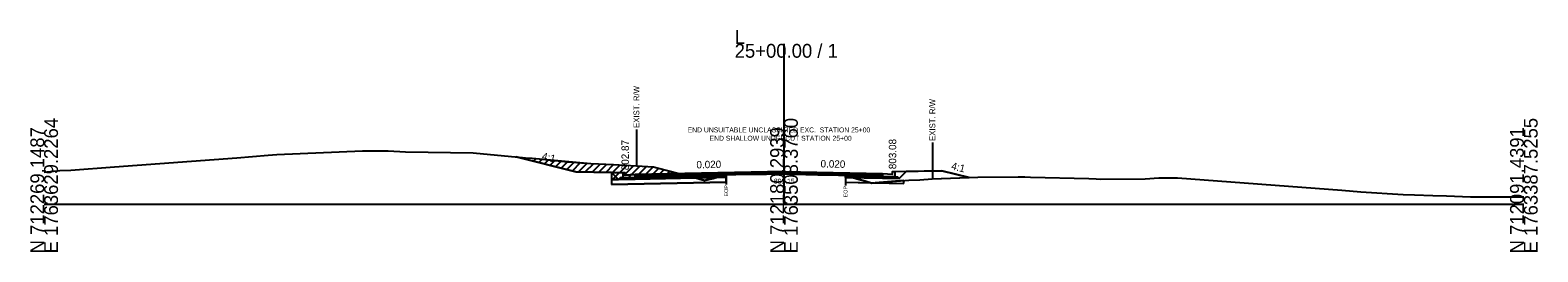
# Model space of a CAD drawing. Extents: x -26 to 5303, y -10 to 9578.
# Drawn here: x 997.2 to 1302.8, y 4990.3 to 5035.3 of the extents above; entities that cross this region are included whole.
import ezdxf

# ---------------------------------------------------------------- set-up
doc = ezdxf.new("R2010")
doc.units = 0
for name, color, linetype in [('Default', 7, 'Continuous'), ('Exist CMT Pavement', 7, 'Continuous'), ('Exist Cross Section Cell', 7, 'Continuous'), ('Exist XS Ground Line', 7, 'Continuous'), ('Old_Level_10', 7, 'Continuous'), ('Old_Level_3', 7, 'Continuous'), ('Old_Level_4', 7, 'Continuous'), ('Prop CMT Conc Surface', 7, 'Continuous'), ('Prop CMT Concrete Structures', 7, 'Continuous'), ('Prop CMT Pvmt Course 1', 7, 'Continuous'), ('Prop CMT Pvmt Course 1 CG', 7, 'Continuous'), ('Prop CMT Pvmt Course 2', 7, 'Continuous'), ('Prop CMT Pvmt Course 3', 7, 'Continuous'), ('Prop CMT Pvmt Surface', 7, 'Continuous'), ('Prop CMT Slope Grass', 7, 'Continuous'), ('Prop CMT Subgrade Earthwork', 7, 'Continuous'), ('Prop Shade Light', 7, 'Continuous'), ('Prop XS Earthwork Shape', 7, 'Continuous'), ('Prop XS Hydro Elevations', 7, 'Continuous'), ('Prop XS SE Text', 7, 'Continuous'), ('Prop XS Side Slope Text', 7, 'Continuous'), ('Prop XS Wedging', 7, 'Continuous'), ('Scratch_Level_5', 7, 'Continuous')]:
    doc.layers.add(name, color=color, linetype=linetype)

msp = doc.modelspace()

# ---------------------------------------------------------------- linework, layer by layer
at = {"layer": 'Exist CMT Pavement'}
msp.add_lwpolyline([(1138.28, 5006), (1138.28, 5006), (1139.74, 5006.03), (1140.23, 5006.03), (1141.01, 5006.04), (1143.33, 5006.07), (1144.17, 5006.08), (1145.47, 5006.09), (1146.43, 5006.1), (1147.26, 5006.11), (1148.39, 5006.13), (1149.26, 5006.14), (1150, 5006.15), (1150.45, 5006.15), (1150.95, 5006.12), (1151.5, 5006.1), (1152.64, 5006.06), (1154.41, 5006.03), (1155.74, 5006), (1156.2, 5005.99), (1156.83, 5005.97), (1157.99, 5005.94), (1158.84, 5005.92), (1159.78, 5005.91), (1161.05, 5005.87), (1161.68, 5005.86), (1162.48, 5005.82)], dxfattribs=at)
at = {"layer": 'Exist Cross Section Cell'}
for p, q in [((1150, 5000), (1150, 5032.5)), ((1000, 5000), (1150, 5000)), ((1150, 5000), (1300, 5000))]:
    msp.add_line(p, q, dxfattribs=at)
at = {"layer": 'Exist XS Ground Line'}
msp.add_lwpolyline([(1000, 5006.5), (1003.18, 5006.81), (1005.43, 5006.9), (1014.28, 5007.58), (1039.05, 5009.41), (1045.43, 5009.93), (1047.15, 5010.06), (1064.54, 5010.83), (1066.19, 5010.83), (1067.13, 5010.83), (1068.84, 5010.83), (1069.75, 5010.78), (1073.25, 5010.63), (1087.01, 5010.38), (1097.56, 5009.42), (1098.95, 5009.32), (1099.65, 5009.25), (1110.84, 5008.27), (1115.41, 5008.02), (1122.42, 5007.61), (1123.53, 5007.54), (1124.29, 5007.35), (1131.11, 5005.63), (1133.88, 5004.78), (1135.64, 5005.2), (1138.28, 5006), (1139.74, 5006.03), (1140.23, 5006.03), (1141.9, 5006.06), (1143.33, 5006.07), (1144.17, 5006.08), (1145.47, 5006.09), (1146.43, 5006.1), (1147.26, 5006.11), (1148.39, 5006.13), (1149.26, 5006.14), (1150, 5006.15), (1150.45, 5006.15), (1150.95, 5006.12), (1151.5, 5006.1), (1152.73, 5006.06), (1155.74, 5006), (1156.2, 5005.99), (1156.83, 5005.97), (1157.99, 5005.94), (1158.84, 5005.92), (1159.78, 5005.91), (1161.05, 5005.87), (1161.68, 5005.86), (1162.48, 5005.82), (1166.67, 5004.56), (1167.81, 5004.25), (1175.33, 5004.87), (1177.57, 5004.9), (1180.06, 5005.1), (1189.32, 5005.44), (1197.45, 5005.55), (1198.38, 5005.53), (1198.86, 5005.53), (1199.98, 5005.45), (1211.81, 5005.17), (1213.28, 5005.14), (1214.27, 5005.08), (1223.21, 5005.14), (1226.01, 5005.35), (1229.8, 5005.36), (1263.08, 5002.85), (1266.95, 5002.5), (1275.56, 5001.97), (1277.86, 5001.89), (1281.56, 5001.74), (1284.32, 5001.65), (1289.21, 5001.47), (1293.51, 5001.5), (1300, 5001.46)], dxfattribs=at)
at = {"layer": 'Old_Level_10'}
for p, q in [((1120.08, 5015.15), (1120.08, 5007.75)), ((1180.08, 5012.51), (1180.08, 5005.1)), ((1138.28, 5006), (1138.28, 5003.95)), ((1162.48, 5005.82), (1162.48, 5003.77))]:
    msp.add_line(p, q, dxfattribs=at)
at = {"layer": 'Prop CMT Conc Surface'}
for points in [[(1117.8, 5005.87), (1117.8, 5006.37), (1117.3, 5006.37)], [(1119.8, 5005.99), (1117.8, 5005.87)], [(1170, 5006.2), (1172, 5006.08)], [(1172, 5006.08), (1172, 5006.58), (1172.5, 5006.58)]]:
    msp.add_lwpolyline(points, dxfattribs=at)
at = {"layer": 'Prop CMT Concrete Structures'}
for points in [[(1119.8, 5005.99), (1117.8, 5005.87), (1117.8, 5006.37), (1117.3, 5006.37)], [(1117.3, 5006.37), (1117.3, 5005.36), (1119.8, 5005.41)], [(1119.8, 5005.41), (1119.8, 5005.99)], [(1170, 5006.2), (1172, 5006.08), (1172, 5006.58), (1172.5, 5006.58)], [(1172.5, 5006.58), (1172.5, 5005.56), (1170, 5005.61)], [(1170, 5005.61), (1170, 5006.2)]]:
    msp.add_lwpolyline(points, dxfattribs=at)
at = {"layer": 'Prop CMT Pvmt Course 1'}
for points in [[(1150, 5006.6), (1119.8, 5005.99)], [(1119.8, 5005.74), (1138.28, 5006.11)], [(1119.8, 5005.99), (1119.8, 5005.74)], [(1138.28, 5006.11), (1150, 5006.35)], [(1138.28, 5006.11), (1138.28, 5006.11)], [(1150, 5006.35), (1150, 5006.6)], [(1150, 5006.6), (1170, 5006.2)], [(1150, 5006.35), (1150, 5006.35), (1150, 5006.35)], [(1162.48, 5006.1), (1150, 5006.35)], [(1170, 5005.95), (1162.48, 5006.1)], [(1162.48, 5006.1), (1162.48, 5006.1)], [(1170, 5006.2), (1170, 5005.95)]]:
    msp.add_lwpolyline(points, dxfattribs=at)
at = {"layer": 'Prop CMT Pvmt Course 1 CG'}
for points in [[(1119.8, 5005.41), (1116.8, 5005.35), (1116.46, 5005.01)], [(1116.46, 5005.01), (1119.8, 5005.07)], [(1119.8, 5005.07), (1119.8, 5005.41)], [(1170, 5005.61), (1173, 5005.55), (1173.34, 5005.21)], [(1170, 5005.28), (1170, 5005.61)], [(1173.34, 5005.21), (1170, 5005.28)]]:
    msp.add_lwpolyline(points, dxfattribs=at)
at = {"layer": 'Prop CMT Pvmt Course 2'}
for points in [[(1138.28, 5006.11), (1119.8, 5005.74)], [(1119.8, 5005.41), (1138.28, 5005.78)], [(1119.8, 5005.74), (1119.8, 5005.41)], [(1138.28, 5005.78), (1138.28, 5006.11)], [(1162.48, 5005.76), (1162.48, 5006.1)], [(1162.48, 5006.1), (1170, 5005.95)], [(1170, 5005.61), (1162.48, 5005.76)], [(1170, 5005.95), (1170, 5005.61)]]:
    msp.add_lwpolyline(points, dxfattribs=at)
at = {"layer": 'Prop CMT Pvmt Course 3'}
for points in [[(1138.28, 5005.78), (1119.8, 5005.41)], [(1119.8, 5005.07), (1138.28, 5005.44)], [(1119.8, 5005.41), (1119.8, 5005.07)], [(1138.28, 5005.44), (1138.28, 5005.78)], [(1162.48, 5005.76), (1170, 5005.61)], [(1162.48, 5005.43), (1162.48, 5005.76)], [(1170, 5005.28), (1162.48, 5005.43)], [(1170, 5005.61), (1170, 5005.28)]]:
    msp.add_lwpolyline(points, dxfattribs=at)
at = {"layer": 'Prop CMT Pvmt Surface'}
for points in [[(1150, 5006.6), (1119.8, 5005.99)], [(1150, 5006.6), (1170, 5006.2)]]:
    msp.add_lwpolyline(points, dxfattribs=at)
at = {"layer": 'Prop CMT Slope Grass'}
for points in [[(1117.3, 5006.37), (1107.8, 5006.56), (1095.68, 5009.59)], [(1172.5, 5006.58), (1182, 5006.77), (1187.55, 5005.38)]]:
    msp.add_lwpolyline(points, dxfattribs=at)
at = {"layer": 'Prop CMT Subgrade Earthwork'}
for p, q in [((1138.28, 5005.44), (1138.28, 5006)), ((1162.48, 5005.82), (1162.48, 5005.82)), ((1162.48, 5005.82), (1162.48, 5005.43))]:
    msp.add_line(p, q, dxfattribs=at)
for points in [[(1119.8, 5005.07), (1116.46, 5005.01), (1115.05, 5006.42)], [(1138.28, 5005.44), (1119.8, 5005.07)], [(1162.48, 5005.43), (1170, 5005.28)], [(1170, 5005.28), (1173.34, 5005.21), (1174.75, 5006.62)]]:
    msp.add_lwpolyline(points, dxfattribs=at)
at = {"layer": 'Prop Shade Light'}
for p, q in [((1116.46, 5005.01), (1115.05, 5004.98)), ((1115.05, 5004.98), (1115.05, 5003.98)), ((1115.05, 5004.98), (1115.05, 5003.98)), ((1115.05, 5003.98), (1138.28, 5004.44)), ((1119.8, 5005.07), (1116.46, 5005.01)), ((1132.12, 5005.32), (1119.8, 5005.07)), ((1138.28, 5005.44), (1136.12, 5005.4)), ((1138.28, 5005.48), (1138.28, 5004.44)), ((1138.28, 5004.44), (1138.28, 5005.44)), ((1162.48, 5005.47), (1162.48, 5004.43)), ((1162.48, 5005.43), (1162.48, 5004.43)), ((1163.88, 5005.4), (1162.48, 5005.43)), ((1162.48, 5004.43), (1167.54, 5004.33)), ((1174.28, 5004.78), (1168.48, 5004.31)), ((1168.48, 5004.31), (1174.28, 5004.19)), ((1174.28, 5004.19), (1174.28, 5004.78))]:
    msp.add_line(p, q, dxfattribs=at)
for points in [[(1138.28, 5004.44), (1115.05, 5003.98)], [(1136.12, 5005.4), (1133.88, 5004.78), (1132.12, 5005.32)], [(1162.48, 5004.43), (1174.28, 5004.19)], [(1167.54, 5004.33), (1166.67, 5004.56), (1163.88, 5005.4)]]:
    msp.add_lwpolyline(points, dxfattribs=at)
at = {"layer": 'Prop XS Earthwork Shape'}
for points in [[(1117.8, 5005.87), (1117.8, 5006.37), (1117.3, 5006.37), (1115.05, 5006.42), (1107.8, 5006.56), (1095.68, 5009.59), (1097.56, 5009.42), (1098.95, 5009.32), (1099.65, 5009.25), (1106.1, 5008.6), (1110.84, 5008.27), (1115.41, 5008.02), (1122.42, 5007.61), (1123.53, 5007.54), (1124.29, 5007.35), (1128.95, 5006.17), (1119.8, 5005.99)], [(1119.8, 5005.07), (1116.46, 5005.01), (1115.05, 5006.42), (1117.3, 5006.37), (1117.8, 5006.37), (1117.8, 5005.87), (1119.8, 5005.99), (1128.95, 5006.17), (1131.11, 5005.63), (1132.12, 5005.32)], [(1133.88, 5004.78), (1136.12, 5005.4), (1132.12, 5005.32)], [(1138.28, 5005.44), (1138.28, 5006), (1136.12, 5005.4)], [(1162.48, 5005.82), (1163.88, 5005.4), (1162.48, 5005.43)], [(1177.57, 5004.9), (1180.06, 5005.1), (1187.55, 5005.38), (1182, 5006.77), (1174.75, 5006.62), (1173.34, 5005.21), (1170, 5005.28), (1163.88, 5005.4), (1166.67, 5004.56), (1167.81, 5004.25), (1175.33, 5004.87)]]:
    msp.add_lwpolyline(points, close=True, dxfattribs=at)
at = {"layer": 'Prop XS Hydro Elevations'}
msp.add_line((1115.05, 5004.98), (1116.46, 5005.01), dxfattribs=at)
at = {"layer": 'Prop XS Wedging'}
for points in [[(1138.28, 5006), (1138.28, 5006.11), (1139.74, 5006.14), (1140.23, 5006.15), (1141.01, 5006.17), (1143.33, 5006.21), (1144.17, 5006.23), (1145.47, 5006.25), (1146.43, 5006.27), (1147.26, 5006.29), (1148.39, 5006.31), (1149.26, 5006.33), (1150, 5006.35), (1150.45, 5006.34), (1150.95, 5006.33), (1151.5, 5006.32), (1152.64, 5006.29), (1154.41, 5006.26), (1155.74, 5006.23), (1156.2, 5006.22), (1156.83, 5006.21), (1157.99, 5006.19), (1158.85, 5006.17), (1159.78, 5006.15), (1161.05, 5006.12), (1161.68, 5006.11), (1162.48, 5006.1), (1162.48, 5005.82), (1161.68, 5005.86), (1161.05, 5005.87), (1159.78, 5005.91), (1158.85, 5005.92), (1157.99, 5005.94), (1156.83, 5005.97), (1156.2, 5005.99), (1155.74, 5006), (1154.41, 5006.03), (1152.64, 5006.06), (1151.5, 5006.1), (1150.95, 5006.12), (1150.45, 5006.15), (1150, 5006.15), (1149.26, 5006.14), (1148.39, 5006.13), (1147.26, 5006.11), (1146.43, 5006.1), (1145.47, 5006.09), (1144.17, 5006.08), (1143.33, 5006.07), (1141.01, 5006.04), (1140.23, 5006.03), (1139.74, 5006.03)], [(1151.04, 5006.12), (1151.24, 5006.32), (1151.5, 5006.32), (1152.64, 5006.29), (1154.41, 5006.26), (1155.74, 5006.23), (1156.2, 5006.22), (1156.83, 5006.21), (1157.99, 5006.19), (1158.85, 5006.17), (1159.78, 5006.15), (1161.05, 5006.12), (1161.68, 5006.11), (1162.48, 5006.1), (1162.48, 5005.82), (1161.68, 5005.86), (1161.05, 5005.87), (1159.78, 5005.91), (1158.85, 5005.92), (1157.99, 5005.94), (1156.83, 5005.97), (1156.2, 5005.99), (1155.74, 5006), (1154.41, 5006.03), (1152.64, 5006.06), (1151.5, 5006.1)]]:
    msp.add_lwpolyline(points, close=True, dxfattribs=at)
at = {"layer": 'Scratch_Level_5'}
for p, q in [((1095.68, 5009.59), (1107.8, 5006.56)), ((1095.78, 5009.57), (1095.8, 5009.58)), ((1096.92, 5009.28), (1097.1, 5009.46)), ((1098.05, 5009), (1098.41, 5009.36)), ((1099.18, 5008.72), (1099.71, 5009.25)), ((1100.31, 5008.43), (1100.99, 5009.11)), ((1101.44, 5008.15), (1102.27, 5008.98)), ((1102.57, 5007.87), (1103.56, 5008.85)), ((1103.7, 5007.59), (1104.84, 5008.72)), ((1104.84, 5007.3), (1106.13, 5008.59)), ((1105.97, 5007.02), (1107.45, 5008.5)), ((1107.1, 5006.74), (1108.77, 5008.41)), ((1108.33, 5006.55), (1110.1, 5008.32)), ((1109.71, 5006.52), (1111.43, 5008.24)), ((1111.1, 5006.5), (1112.77, 5008.17)), ((1112.49, 5006.47), (1114.11, 5008.09)), ((1113.87, 5006.44), (1115.45, 5008.02)), ((1115.05, 5006.21), (1116.79, 5007.94)), ((1115.24, 5004.98), (1118.12, 5007.86)), ((1116.69, 5005.01), (1119.46, 5007.78)), ((1118.13, 5005.04), (1120.79, 5007.7)), ((1119.57, 5005.07), (1122.13, 5007.63)), ((1121.02, 5005.1), (1123.47, 5007.55)), ((1122.46, 5005.13), (1124.6, 5007.27)), ((1107.8, 5006.56), (1115.05, 5006.42)), ((1115.05, 5006.42), (1115.05, 5004.98)), ((1123.9, 5005.16), (1125.73, 5006.99)), ((1125.35, 5005.19), (1126.86, 5006.7)), ((1126.79, 5005.21), (1127.99, 5006.42)), ((1128.23, 5005.24), (1129.12, 5006.13)), ((1129.68, 5005.27), (1130.25, 5005.85)), ((1131.12, 5005.3), (1131.37, 5005.55)), ((1136.15, 5005.4), (1136.16, 5005.41)), ((1137.59, 5005.43), (1138.12, 5005.95))]:
    msp.add_line(p, q, dxfattribs=at)

# ---------------------------------------------------------------- texts
at = {"layer": 'Default'}
msp.add_text('-', height=0.0001, dxfattribs=at).set_placement((1000, 5000))
at = {"layer": 'Exist Cross Section Cell'}
for s, p in [('L', (1140, 5032.5)), ('25+00.00 / 1', (1140, 5029.7))]:
    msp.add_text(s, height=2.8, dxfattribs=at).set_placement(p)
for s, p in [('E 1763629.2264', (1002.8, 4990)), ('E 1763508.3760', (1152.8, 4990)), ('E 1763387.5255', (1302.8, 4990)), ('N 712269.1487', (1000, 4990)), ('N 712180.2939', (1150, 4990)), ('N 712091.4391', (1300, 4990))]:
    msp.add_text(s, height=2.8, rotation=90, dxfattribs=at).set_placement(p)
at = {"layer": 'Old_Level_10'}
for s, height, p in [('EXIST. R/W', 1.181, (1120.67, 5015.45)), ('EXIST. R/W', 1.181, (1180.67, 5012.81)), ('EOP', 0.787, (1138.67, 5001.55)), ('EOP', 0.787, (1162.87, 5001.37))]:
    msp.add_text(s, height=height, rotation=90, dxfattribs=at).set_placement(p)
at = {"layer": 'Old_Level_3'}
msp.add_text('803.15', height=1, dxfattribs=at).set_placement((1147.95, 5004.15))
at = {"layer": 'Old_Level_4'}
msp.add_text('END SHALLOW UNDERCUT STATION 25+00', height=1, dxfattribs=at).set_placement((1134.91, 5012.86))
at = {"layer": 'Prop XS Hydro Elevations'}
for s, p in [('802.87', (1118.55, 5006.87)), ('803.08', (1172.75, 5007.08))]:
    msp.add_text(s, height=1.5, rotation=90, dxfattribs=at).set_placement(p)
at = {"layer": 'Prop XS SE Text'}
for rotation, p in [(1.1458, (1132.26, 5007.24)), (358.8542, (1157.4, 5007.45))]:
    msp.add_text('0.020', height=1.5, rotation=rotation, dxfattribs=at).set_placement(p)
at = {"layer": 'Prop XS Side Slope Text'}
for p in [(1100.77, 5009.09), (1183.8, 5007.09)]:
    msp.add_text('4:1', height=1.5, rotation=345.9638, dxfattribs=at).set_placement(p)
at = {"layer": 'Scratch_Level_5'}
msp.add_text('END UNSUITABLE UNCLASSIFIED EXC.  STATION 25+00', height=1, dxfattribs=at).set_placement((1130.46, 5014.55))

doc.saveas('drawing.dxf')
